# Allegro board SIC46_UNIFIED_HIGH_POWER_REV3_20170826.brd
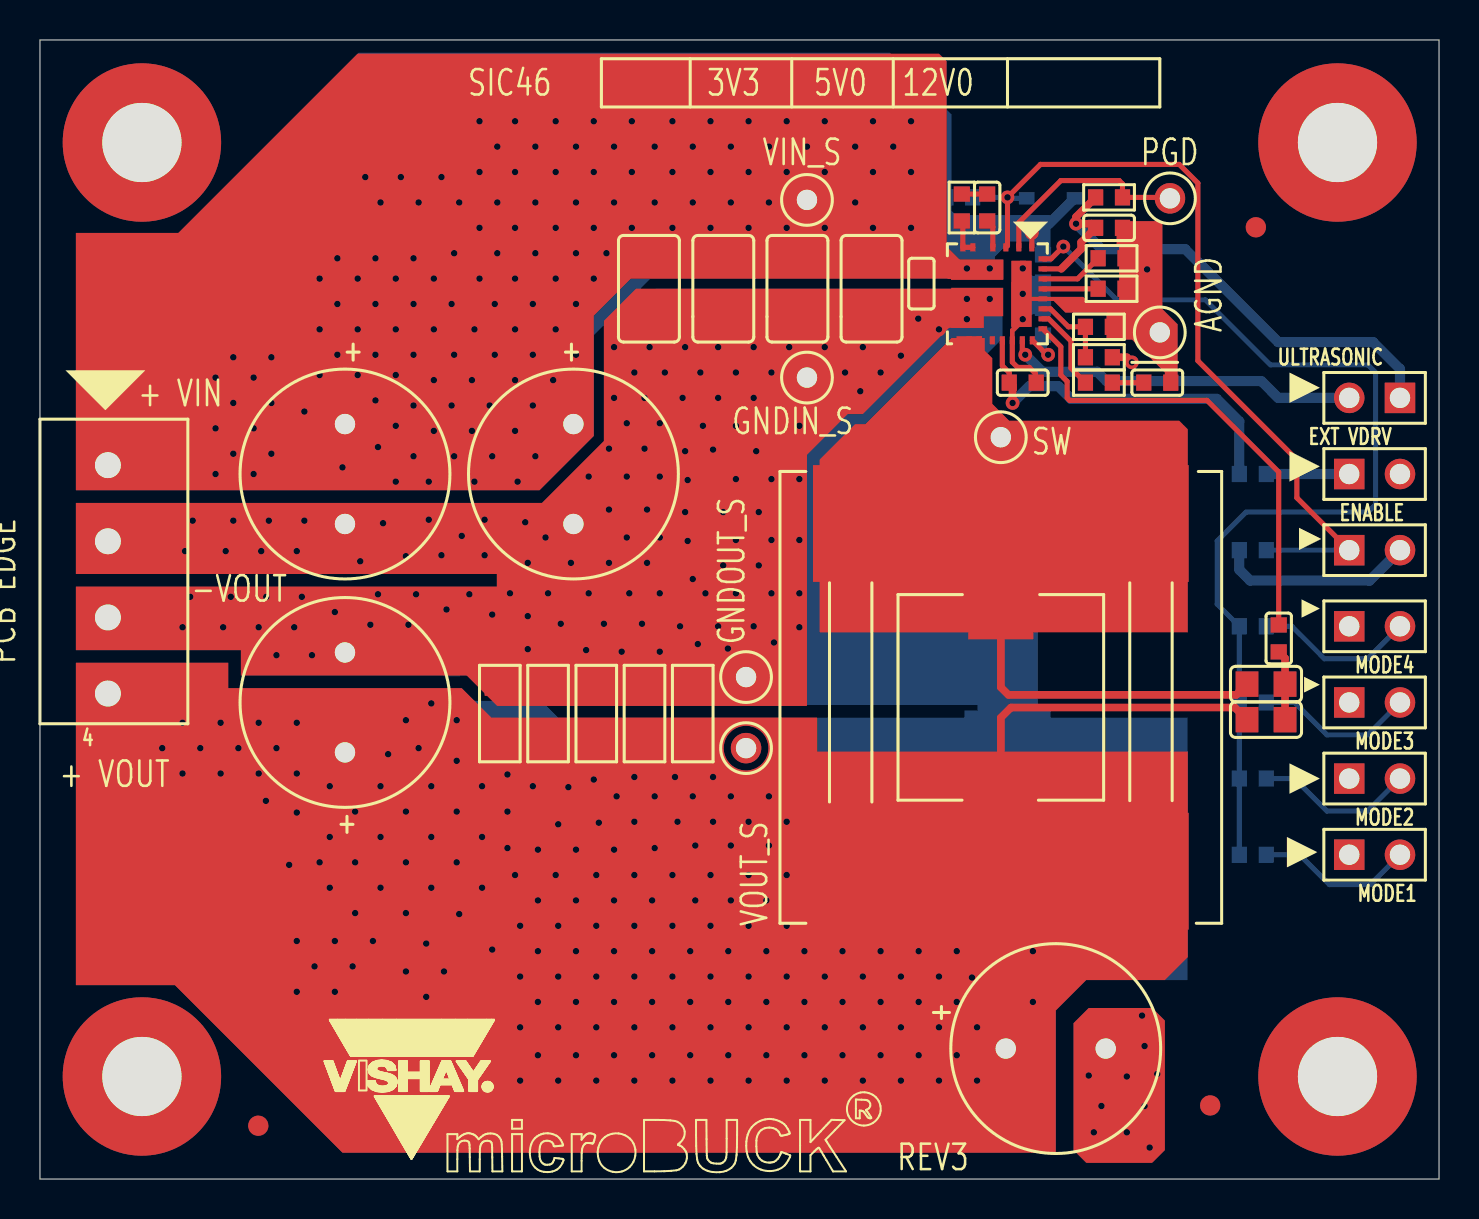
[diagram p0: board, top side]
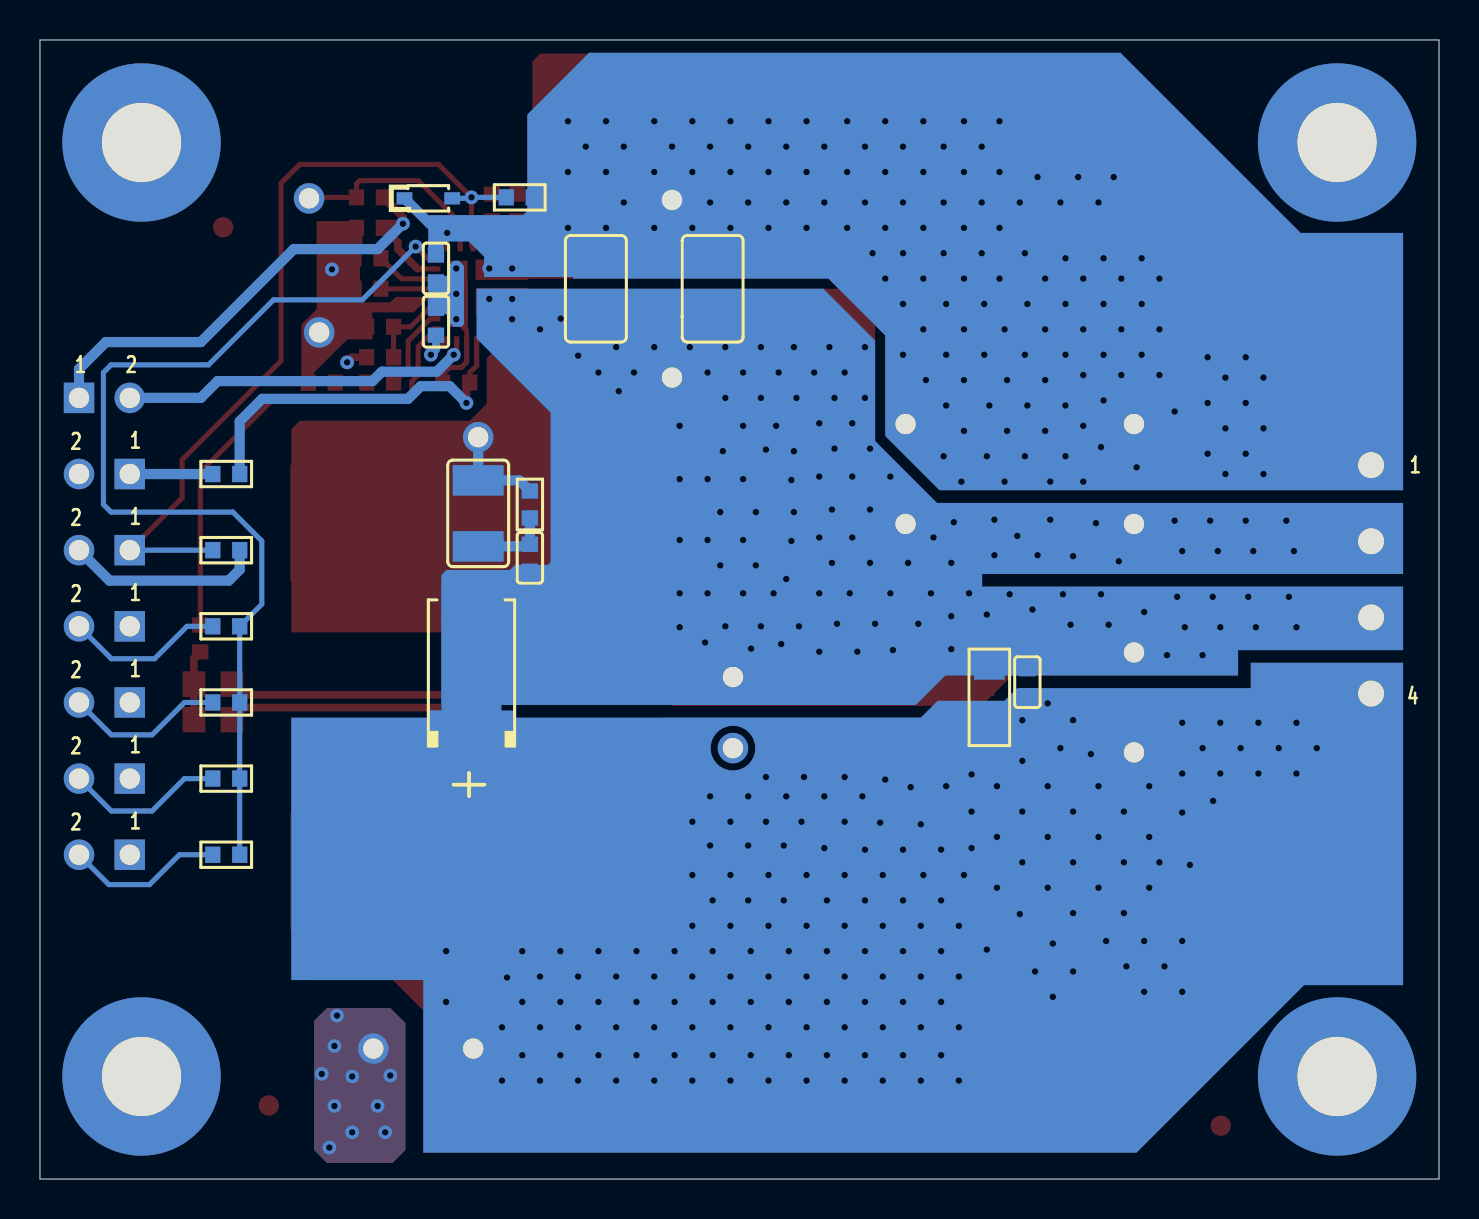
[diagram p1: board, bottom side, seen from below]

Outline 70 x 57 mm; copper layers: TOP, INNER_LAYER2, INNER_LAYER3, INNER_LAYER4, INNER_LAYER5, BOTTOM. Coordinates in mm from the lower left corner of the outline.
Outline path: 0,57 0,0 70,0 70,57 0,57

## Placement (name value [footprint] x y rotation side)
C1  0.1uF  [C0603]  47.39 48.61 270 top
C2  0.1uF  [C0603]  50.19 45.56 90 bottom
C3  1uF  [C0603]  53.49 47.6 180 top
C4  2.2uF  [C1210]  36.34 44.55 90 bottom
C5  2.2uF  [C1210]  37.9 44.55 90 top
C6  2.2uF  [C1210]  41.61 44.55 90 top
C7  2.2uF  [C1210]  42.18 44.55 90 bottom
C8  0.1uF  [C0603]  44.1 44.81 270 top
C9  1nF  [C0603]  55.9 39.85 180 top
C10  22nF  [C0603]  50.19 42.9 90 bottom
C11  4.7uF  [C0603]  49.17 39.85 180 top
C12  2.2nF  [C0603]  61.98 27.05 270 top
C13  22nF  [C0805]  61.34 22.99 180 top
C14  0.1uF  [C0603]  20.59 24.86 270 bottom
C15  22uF  [C1206]  30.25 23.29 270 top
C16  22uF  [C1206]  25.42 23.29 270 top
C17  22uF  [C1206]  22.5 24.1 270 bottom
C18  22uF  [C1206]  32.66 23.29 270 top
C19  22uF  [C1206]  23.01 23.29 270 top
C20  22uF  [C1206]  27.83 23.29 270 top
C21  DNP  [C0603]  45.49 31.09 270 bottom
C22  100uF 63V  [MAL215058101E3]  26.69 35.28 270 top
C23  470u, 2V  [T_D27_7343]  48.41 25.32 90 bottom
C24  100uF 63V  [MAL215058101E3]  50.82 6.53 0 top
C25  2.2uF  [C1210]  34.19 44.55 90 top
C26  2.2uF  [C1210]  30.47 44.55 90 top
C27  100uF 63V  [MAL215058101E3]  15.26 23.85 90 top
C28  100uF 63V  [MAL215058101E3]  15.26 35.28 270 top
D1  DNP  [BZX384C3V3]  50.57 49.07 0 bottom
J1  JUMPER  [22-28-4023]  65.5 16.23 0 top
J2  JUMPER  [22-28-4023]  65.5 20.04 0 top
J3  JUMPER  [22-28-4023]  65.5 23.85 0 top
J4  JUMPER  [22-28-4023]  65.5 27.66 0 top
J5  CON4  [20020327-D041B01LF]  3.4 35.72 270 top
J6  PGD  [5002]  56.54 49.07 0 top
J7  EN  [22-28-4023]  65.5 35.28 0 top
J8  JUMPER  [22-28-4023]  68.04 39.09 180 top
J9  EN  [22-28-4023]  65.5 31.47 0 top
J10  GND  [5002]  56.03 42.36 0 top
L1  DNP  [IHLP-4040]  48.07 24.1 90 top
L2  3.3uH  [IHLP-5050]  48.07 24.1 90 top
L3  DNP  [IHLP-6767]  48.07 24.1 90 top
L4  DNP  [IHLP-8787]  48.07 24.1 180 top
NOREF  -  []  16.47 44.29 0 top
NOREF#2  -  []  70.74 -17.94 90 top
NOREF#3  -  []  33.17 -43.2 90 top
NOREF#4  -  []  70 0 90 top
NOREF#5  -  []  126.76 1.25 0 top
NOREF#6  -  [unnamed#2]  58.55 3.68 0 top
NOREF#7  -  []  33.17 6.33 90 top
NOREF#8  -  []  38.82 1.68 90 top
NOREF#9  -  []  146.18 -25.56 90 top
NOREF#10  -  []  81.94 73 0 top
NOREF#11  -  []  210.87 -24.79 0 top
NOREF#12  -  []  159.41 73 90 top
NOREF#13  -  []  119.04 -0.16 90 top
NOREF#14  -  []  173.38 73 0 top
NOREF#15  -  []  10.82 -47.85 0 top
NOREF#16  -  []  33.17 31.09 90 top
NOREF#17  -  []  70.74 -43.34 90 top
NOREF#18  -  []  33.17 55.86 90 top
NOREF#19  -  []  158.41 74.5 90 top
NOREF#20  -  [unnamed#2]  60.83 47.62 0 top
NOREF#21  -  []  146.18 7.46 0 top
NOREF#22  -  []  144.44 76 0 top
NOREF#23  -  []  0 38.02 0 top
NOREF#24  -  []  22.82 19.53 0 top
NOREF#25  -  []  130.11 -10.9 0 top
NOREF#26  -  []  119.04 -17.94 90 top
NOREF#27  -  []  29.17 -5.24 0 top
NOREF#28  -  []  3.4 35.72 90 top
NOREF#29  -  []  146.18 -35.72 90 top
NOREF#30  -  []  10.82 -23.09 0 top
NOREF#31  -  []  74.57 29.05 0 top
NOREF#32  -  []  29.17 19.53 0 top
NOREF#33  -  []  22.82 44.29 0 top
NOREF#34  -  []  16.47 69.06 0 top
NOREF#35  -  []  10.82 1.68 0 top
NOREF#36  -  []  16.47 19.53 0 top
NOREF#37  -  []  29.17 -30 0 top
NOREF#38  -  []  10.82 51.21 0 top
NOREF#39  -  []  0 57 0 top
NOREF#40  -  []  159.41 73 0 top
NOREF#41  -  []  70.74 -43.34 0 top
NOREF#42  -  []  80.94 74.5 90 top
NOREF#43  -  []  119.04 -17.94 90 top
NOREF#44  -  []  194.48 -43.34 90 top
NOREF#45  -  []  146.18 -25.56 90 top
NOREF#46  -  [unnamed#2]  64.92 5.13 0 top
NOREF#47  -  [unnamed#2]  5.1 51.87 0 top
NOREF#48  -  []  145.44 73 90 top
NOREF#49  -  []  205.1 -35.23 0 top
NOREF#50  -  []  173.38 73 90 top
NOREF#51  -  [unnamed#2]  64.92 51.87 0 top
NOREF#52  -  []  119.04 -35.72 90 top
NOREF#53  -  []  146.18 -10.32 90 top
NOREF#54  -  []  29.17 69.06 0 top
NOREF#55  -  []  15.24 38.02 90 top
NOREF#56  -  []  194.48 -17.94 90 top
NOREF#57  -  []  3.4 31.91 90 top
NOREF#58  -  []  145.44 73 0 top
NOREF#59  -  []  38.82 -23.09 90 top
NOREF#60  -  []  38.82 -47.85 90 top
NOREF#61  -  []  144.44 74.5 90 top
NOREF#62  -  []  119.04 -10.32 90 top
NOREF#63  -  []  80.94 76 0 top
NOREF#64  -  []  67.97 73 90 top
NOREF#65  -  [unnamed#2]  5.1 5.13 0 top
NOREF#66  -  []  66.97 76 0 top
NOREF#67  -  []  33.17 -18.44 90 top
NOREF#68  -  []  130.45 2.13 90 top
NOREF#69  -  []  70.74 -28.1 90 top
NOREF#70  -  []  22.82 -5.24 0 top
NOREF#71  -  []  146.18 -17.94 90 top
NOREF#72  -  []  131.29 -7.52 0 top
NOREF#73  -  []  -25.63 -29.6 0 top
NOREF#74  -  []  0 45.42 0 top
NOREF#75  -  []  146.18 -43.34 90 top
NOREF#76  -  []  22.82 -30 0 top
NOREF#77  -  []  194.48 -28.1 90 top
NOREF#78  -  []  172.38 76 0 top
NOREF#79  -  []  68.79 18.62 0 top
NOREF#80  -  []  81.94 73 90 top
NOREF#81  -  []  29.17 44.29 0 top
NOREF#82  -  []  132.74 -40.21 90 top
NOREF#83  -  []  172.38 74.5 90 top
NOREF#84  -  []  38.82 51.21 90 top
NOREF#85  -  []  66.97 74.5 90 top
NOREF#86  -  []  10.82 26.44 0 top
NOREF#87  -  []  -57.13 -63.4 0 top
NOREF#88  -  []  158.41 76 0 top
NOREF#89  -  []  38.82 26.44 90 top
NOREF#90  -  [unnamed#2]  10.92 2.67 0 top
NOREF#91  -  []  22.82 69.06 0 top
NOREF#92  -  []  67.97 73 0 top
NOREF#93  -  []  119.04 -25.56 90 top
NOREF#94  -  []  16.47 -5.24 0 top
NOREF#95  -  []  129.05 -41.09 0 top
NOREF#96  -  []  16.47 -30 0 top
R1  102K  [R0603]  53.49 49.12 180 top
R2  3.3  [R0603]  46.12 48.61 90 top
R3  560K  [R0603]  45.99 49.12 0 bottom
R4  53.6K  [R0603]  53.61 46.07 180 top
R5  2K  [R0603]  60.68 16.23 0 bottom
R6  301K  [R0603]  60.68 20.04 0 bottom
R7  499K  [R0603]  60.68 23.85 0 bottom
R8  1M  [R0603]  60.68 27.66 0 bottom
R9  53.6K  [R0603]  53.61 44.55 180 top
R10  10K  [R0603]  52.98 42.64 180 top
R11  19.6K  [R0603]  52.98 39.85 180 top
R12  52.3K  [R0603]  52.98 41.12 0 top
R14  DNP  [R0603]  60.68 35.28 180 bottom
R15  DNP  [R0805]  61.34 24.77 180 top
R16  DNP  [R0603]  45.49 33.75 270 bottom
R16A  DNP  [R1210]  48.07 33.31 270 bottom
R17  DNP  [R0603]  60.68 31.47 0 bottom
TP1  test point  [5002]  38.37 48.99 0 top
TP2  test point  [5002]  38.37 40.1 0 top
TP3  test point  [5002]  35.33 21.56 0 top
TP4  test point  [5002]  35.33 25.12 90 top
TP11  5002  [PAD040_060_SQ]  48.07 37.12 0 top
U1  SiC46X  [5MMX5MM]  47.9 44.29 270 top

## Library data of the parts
C1-C21 C25 C26 = CAP NP
C22 C24 C27 C28 = CAP POL
C23 = CAP, TA-P,V,470u, 2V_0: User Part Number: PN; Tolerance: TOL
D1 = DIODE ZENER
J1-J4 J8 = JUMPER
J5 = HEADER 4
J6 J10 = HEADER 1
J7 J9 = HEADER 2
L1-L4 = IND
R1-R12 R14-R16 R16A R17 = RESISTOR
TP1-TP4 = TEST POINT
TP11 = TP_0
U1 = SiC462CD-T1-GE3_32

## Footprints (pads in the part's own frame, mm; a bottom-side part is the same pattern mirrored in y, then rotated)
5MMX5MM
  rect 0.406x0.254 smd: 1(-2.325,1.725) 2(-2.325,1.075) 3(-2.325,0.425) 4(-2.325,-0.225) 5(-2.325,-1.225) 6(-2.325,-1.725) 13(2.325,-1.4) 14(2.325,-0.9) 15(2.325,-0.25) 16(2.325,0.25) 17(2.325,0.75) 18(2.325,1.25) 19(2.325,1.75)
  rect 0.254x0.432 smd: 7(-1.525,-2.275) 8(-0.875,-2.275) 9(0.25,-2.275) 10(0.75,-2.275) 11(1.25,-2.275) 20(1.75,2.275) 21(1.25,2.275) 22(0.75,2.275) 23(0.25,2.275) 24(-0.25,2.275) 25(-0.75,2.275) 26(-1.25,2.275) 27(-1.75,2.275)
  rect 0.406x1.27 smd: 12(2.325,-1.408)
  rect 3.302x1.016 smd: 28(0,1.208)
  rect 1.016x2.616 smd: 29(-1.208,-1.008)
  custom 0.5x0.5 smd: 30(0.7,-1.008)
22-28-4023
  rect 1.524x1.524 hole 1.016: 1(0,0)
  round 1.524 hole 1.016: 2(2.54,0)
5002
  round 1.524 hole 1.016: 1(0,0)
20020327-D041B01LF
  rect 2.057x2.057 hole 1.295: 1(0,0)
  round 2.057 hole 1.295: 2(3.81,0) 3(7.62,0) 4(11.43,0)
BZX384C3V3
  rect 0.787x0.61 smd: 1(1.194,0) 2(-1.194,0)
C0603
  rect 0.762x0.813 smd: 1(-0.673,0) 2(0.673,0)
C0805
  rect 1.143x1.27 smd: 1(-0.953,0) 2(0.953,0)
C1206
  rect 1.27x1.524 smd: 1(-1.524,0) 2(1.524,0)
C1210
  rect 1.524x2.54 smd: 1(-1.651,0) 2(1.651,0)
IHLP-4040
  rect 3.124x3.251 smd: 1(-4.47,0) 2(4.47,0)
IHLP-5050
  rect 3.175x3.251 smd: 1(-5.715,0) 2(5.715,0)
IHLP-6767
  rect 3.81x12.319 smd: 1(-8.077,0) 2(8.077,0)
IHLP-8787
  rect 18.796x5.842 smd: 1(0,8.7) 2(0,-8.7)
MAL215058101E3
  rect 1.524x1.524 hole 1.016: 1(-2.5,0)
  round 1.524 hole 1.016: 2(2.5,0)
PAD040_060_SQ
  round 1.524 hole 1.016: 1(0,0)
R0603
  rect 0.762x0.813 smd: 1(-0.673,0) 2(0.673,0)
R0805
  rect 1.143x1.27 smd: 1(-0.953,0) 2(0.953,0)
R1210
  rect 1.524x2.54 smd: 1(-1.651,0) 2(1.651,0)
T_D27_7343
  rect 2.134x2.997 smd: 1(-3.429,0) 3(3.429,0)
  custom 1.079x1.079 smd: 2(0,0)
unnamed#2
  round 1.016 smd: 1(0,0)

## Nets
GND: C4.1 C5.1 C6.1 C7.1 C8.2 C14.1 C15.1 C16.1 C17.1 C18.1 C19.1 C20.1 C21.2 C22.2 C23.2 C23.3 C24.2 C25.1 C26.1 C27.2 C28.2 J5.2 J5.3 J7.2 TP2.1 TP4.1 U1.9(PGND1) U1.10(PGND2) U1.11(PGND3) U1.30(PGND-PAD)
GND_SIGNAL: C2.1 C3.1 C9.1 C10.2 C11.1 J1.1 J2.1 J3.1 J4.1 J9.2 J10.1 R4.1 R9.1 R10.1 R17.1 U1.17(CDRV_RTN) U1.23(AGND) U1.28(AGND-PAD)
VDD1: C3.2 J8.1 R1.2 U1.26(VDD)
VIN: C2.2 C4.2 C5.2 C6.2 C7.2 C8.1 C22.1 C25.2 C26.2 C28.1 D1.1(CATHODE) J5.1 R3.1 TP1.1 U1.1(VCIN) U1.7(VIN1) U1.8(VIN2) U1.29(VIN-PAD)
BOOT: C1.2 U1.4(BOOT)
COMP: R11.2 U1.21(COMP)
ENABLE: D1.2(ANODE) J9.1 R3.2 R17.2 U1.3(EN)
FSW: R9.2 U1.24(FSW)
ILIM: R4.2 U1.25(ILIMIT)
MODE: R5.1 R6.1 R7.1 R8.1 U1.27(MODE)
PGD: J6.1 R1.1 U1.2(PGOOD)
SS: C10.1 U1.19(SS)
ULTRASONIC: J8.2 U1.18(ULTRASONIC)
VDRV: C11.2 R14.2 U1.16(VDRV)
VDRV_IN: J7.1 R14.1
VFB: R10.2 R12.1 U1.22(VFB)
VO: C13.2 C14.2 C15.2 C16.2 C17.2 C18.2 C19.2 C20.2 C23.1 C24.1 C27.1 J5.4 L1.1(A) L2.1(A) L3.1(A) L4.1(A) R12.2 TP3.1
N16770186: R2.1 U1.5(PHASE1) U1.6(PHASE2)
N16770229: C1.1 R2.2
N16771868: C9.2 R11.1
N16772198: J1.2 R5.2
N16772202: J2.2 R6.2
N16772206: J3.2 R7.2
N16773012: C12.2 C13.1 R15.1
N16775181: L1.2(B) L2.2(B) L3.2(B) L4.2(B) R15.2 R16.1 R16A.1 TP11.1 U1.12(SW1) U1.13(SW2) U1.14(SW3)
N16812890: C21.1 R16.2 R16A.2
N16829136: J4.2 R8.2
N16842327: C12.1 U1.20(VSNS)

Pads without a net: NOREF#6 1; NOREF#20 1; NOREF#46 1; NOREF#47 1; NOREF#51 1; NOREF#65 1; NOREF#90 1; U1 15

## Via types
v1: diameter 0.686, hole 0.33, TOP to BOTTOM, 467 vias

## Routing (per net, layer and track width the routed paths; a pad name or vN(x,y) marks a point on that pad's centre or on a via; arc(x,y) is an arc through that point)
GND:
  vias: v1(7.13,27.61) v1(7.26,31.42) v1(7.51,29.13) v1(7.64,32.94) v1(9.16,27.61) v1(9.29,31.42) v1(9.55,29.13) v1(9.67,32.94) v1(10.94,27.61) v1(11.07,31.42) v1(11.32,29.13) v1(11.45,32.94) v1(11.83,26.21) v1(12.72,27.61) v1(12.85,31.42) v1(13.1,29.13) v1(13.23,32.94) v1(13.61,26.21) v1(14.75,28.37) v1(16.02,30.91) v1(16.53,27.74) v1(16.91,29.26) v1(17.17,32.82) v1(18.31,31.17) v1(18.44,27.74) v1(18.82,29.26) v1(19.45,32.99) v1(20.09,31.21) v1(20.34,28.5) v1(21.1,32.18) v1(21.48,29.26) v1(22.25,32.99) v1(22.25,31.21) v1(22.63,28.24) v1(23.52,29.31) v1(24.28,32.86) v1(24.4,30.83) v1(24.4,28.17) v1(24.4,26.51) v1(25.29,32.1) v1(25.42,29.31) v1(26.06,27.78) v1(26.56,30.83) v1(27.33,26.47) v1(27.45,35.15) v1(27.45,29.31) v1(28.21,27.78) v1(28.47,36.55) v1(28.47,33.5) v1(28.47,30.83) v1(28.72,41.63) v1(28.72,39.09) v1(29.1,26.39) v1(29.36,37.82) v1(29.36,35.15) v1(29.36,32.1) v1(29.48,29.31) v1(29.74,40.36) v1(30.12,27.78) v1(30.25,39.09) v1(30.25,36.55) v1(30.37,33.5) v1(30.37,30.83) v1(30.5,41.63) v1(31.01,37.82) v1(31.01,35.15) v1(31.01,32.1) v1(31.01,29.31) v1(31.01,26.39) v1(31.26,40.36) v1(32.02,27.66) v1(32.15,39.09) v1(32.28,41.63) v1(32.28,36.42) v1(32.28,33.37) v1(32.41,34.98) v1(32.41,31.93) v1(32.66,30.02) v1(32.91,26.77) v1(33.04,40.36) v1(33.17,37.69) v1(33.29,29.31) v1(33.68,36.5) v1(33.93,41.63) v1(33.93,39.09) v1(33.93,27.66) v1(34.18,33.37) v1(34.18,30.71) v1(34.42,26.54) v1(34.82,40.36) v1(34.82,37.69) v1(34.82,35.02) v1(34.82,31.98) v1(34.82,29.31) v1(35.71,41.63) v1(35.71,39.09) v1(35.71,27.66) v1(35.83,36.42) v1(35.96,33.37) v1(35.96,30.71) v1(36.6,40.36) v1(36.6,35.02) v1(36.6,31.98) v1(36.6,29.31) v1(36.72,26.85) v1(37.49,41.63) v1(37.99,37.69) v1(37.99,35.02) v1(37.99,31.98) v1(37.99,29.31) v1(37.99,27.61) v1(39.26,41.63) v1(40.28,40.36) v1(41.04,39.42) v1(41.17,41.63) v1(42.06,40.36) v1(43.07,41.2) v1(43.94,43.05) v1(44.98,42.52) v1(46.38,44.04) v1(46.38,43.02) v1(47.52,44.04) v1(52.47,5.18) v1(52.73,2.34) v1(53.11,3.65) v1(54.38,5.13) v1(54.38,2.34) v1(55.14,8.18) v1(55.27,6.65) v1(55.27,3.65) v1(55.52,1.57) v1(55.9,5.26)
GND_SIGNAL: length 12.8
  TOP w0.254: C11.1 49.8,39.89 49.8,40.31 49.5,40.61 48.92,40.61 48.65,40.88 U1.17
  BOTTOM w0.508: R17.1 60.01,30.49 60.55,29.94 66.52,29.94 J9.2
  vias: v1(49.17,45.56) v1(49.17,44.29) v1(49.17,43.02) v1(55.39,45.52)
VDD1: length 27.1
  TOP w0.254: 51.1,45.54 U1.26
  TOP w0.381: 51.1,45.54 52.09,46.53 52.09,46.87 C3.2 52.61,47.8 v1(51.84,47.8) 51.84,48.14 R1.2
  BOTTOM w0.508: v1(51.84,47.8) 53.11,46.53 57.3,46.53 61.95,41.88 66.7,41.88 68.04,40.53 J8.1
VIN: length 2.7
  TOP w0.254: U1.1 v1(49.62,47.34)
  BOTTOM w0.508: D1.1 50.49,47.8 50.31,47.8
  vias: v1(8.78,40.1) v1(8.78,37.56) v1(8.78,35.28) v1(9.67,41.12) v1(9.67,38.83) v1(9.67,36.29) v1(10.69,40.1) v1(10.69,37.56) v1(10.69,35.28) v1(11.58,41.12) v1(11.58,38.83) v1(11.58,36.29) v1(13.23,38.4) v1(13.99,45.06) v1(13.99,42.52) v1(13.99,40.23) v1(14.88,46.07) v1(14.88,43.79) v1(14.88,41.25) v1(15.13,35.61) v1(15.9,45.06) v1(15.9,42.52) v1(15.9,40.23) v1(16.28,50.14) v1(16.78,46.07) v1(16.78,43.79) v1(16.78,41.25) v1(16.78,38.96) v1(16.91,36.63) v1(17.04,48.87) v1(17.8,45.06) v1(17.8,42.52) v1(17.8,40.23) v1(17.8,37.69) v1(17.8,34.9) v1(18.05,50.14) v1(18.69,46.07) v1(18.69,43.79) v1(18.69,41.25) v1(18.69,38.71) v1(18.69,36.17) v1(18.94,48.87) v1(19.45,34.9) v1(19.71,45.06) v1(19.71,42.52) v1(19.71,39.98) v1(19.71,37.44) v1(20.09,50.14) v1(20.59,43.79) v1(20.59,38.71) v1(20.72,46.33) v1(20.72,41.25) v1(20.72,36.17) v1(20.98,48.87) v1(21.61,39.98) v1(21.61,37.44) v1(21.74,42.52) v1(21.74,34.9) v1(21.99,52.93) v1(21.99,50.39) v1(21.99,47.6) v1(21.99,45.06) v1(22.5,38.71) v1(22.63,36.17) v1(22.75,43.79) v1(22.75,41.25) v1(22.88,51.66) v1(22.88,48.87) v1(22.88,46.33) v1(23.77,52.93) v1(23.77,50.39) v1(23.77,47.6) v1(23.77,45.06) v1(23.77,42.52) v1(23.77,39.98) v1(23.77,37.44) v1(23.9,34.9) v1(24.66,43.79) v1(24.66,41.25) v1(24.66,38.71) v1(24.79,51.66) v1(24.79,48.87) v1(24.79,46.33) v1(24.79,36.17) v1(25.67,39.98) v1(25.8,52.93) v1(25.8,50.39) v1(25.8,47.6) v1(25.8,45.06) v1(25.8,42.52) v1(26.82,51.66) v1(26.82,48.87) v1(26.82,46.33) v1(26.82,43.79) v1(26.82,41.25) v1(27.71,52.93) v1(27.71,50.39) v1(27.71,47.6) v1(27.71,45.06) v1(28.34,46.33) v1(28.72,51.66) v1(28.72,48.87) v1(29.61,52.93) v1(29.61,50.39) v1(29.61,47.6) v1(30.75,51.66) v1(30.75,48.87) v1(31.64,52.93) v1(31.64,50.39) v1(31.64,47.6) v1(32.66,51.66) v1(32.66,48.87) v1(33.55,52.93) v1(33.55,50.39) v1(33.55,47.6) v1(34.56,51.66) v1(34.56,48.87) v1(35.45,52.93) v1(35.45,50.39) v1(35.45,47.6) v1(36.47,51.66) v1(36.47,48.87) v1(37.36,52.93) v1(37.36,50.39) v1(37.36,47.6) v1(38.37,51.66) v1(39.26,52.93) v1(39.26,50.39) v1(39.26,47.6) v1(40.79,51.66) v1(40.79,48.87) v1(41.68,52.93) v1(41.68,50.39) v1(41.68,47.6) v1(42.69,51.66) v1(43.58,52.93) v1(43.58,50.39) v1(43.58,47.6) v1(46.38,45.56) v1(47.52,45.56)
BOOT: length 1.4
  TOP w0.254: C1.2 47.67,47.66 U1.4
COMP: length 4.3
  TOP w0.254: R11.2 51.58,40.57 51.58,41.93 50.47,43.04 U1.21
ENABLE: length 41.5
  TOP w0.254: J9.1 62.89,34.09 62.89,35.99 57.93,40.94 57.93,49.83 57,50.77 50.06,50.77 v1(48.41,49.12) 48.41,46.7 U1.3
  BOTTOM w0.254: D1.2 48.46,49.07 v1(48.41,49.12) R3.2 ; R17.2 J9.1
FSW: length 2.8
  TOP w0.254: U1.24 52.94,44.54 R9.2
ILIM: length 3.2
  TOP w0.254: R4.2 51.91,45.04 U1.25
MODE: length 51
  TOP w0.254: U1.27 50.59,46.04 v1(51.2,46.66)
  BOTTOM w0.254: v1(51.2,46.66) 53.87,43.99 58.31,43.99 61.57,40.74 66.44,40.74 66.82,40.36 66.82,33.75 66.44,33.37 60.35,33.37 58.9,31.93 58.9,28.76 R8.1 R7.1 R6.1 R5.1
PGD: length 10.4
  TOP w0.254: J6.1 56.49,49.12 R1.1 54.16,49.8 54,49.96 51.07,49.96 48.97,47.86 U1.2
SS: length 2.2
  TOP w0.254: v1(50.44,41.25) 50.37,41.25 U1.19
  BOTTOM w0.381: C10.1 50.19,41.5 v1(50.44,41.25)
ULTRASONIC: length 17.9
  TOP w0.254: U1.18 49.15,41.39 v1(49.3,41.25)
  BOTTOM w0.508: J8.2 61.95,39.09 61.11,39.93 53.36,39.93 52.89,40.4 50.15,40.4 v1(49.3,41.25)
VDRV: length 18.4
  TOP w0.254: U1.16 48.15,40.69 48.5,40.35 C11.2
  TOP w0.381: v1(48.66,38.83) 48.66,39.68 C11.2
  BOTTOM w0.508: v1(48.66,38.83) 49.5,39.67 50.95,39.67 51.58,39.04 58.88,39.04 60.01,37.91 R14.2
VDRV_IN: length 4.2
  BOTTOM w0.508: J7.1 R14.1
VFB: length 4
  TOP w0.254: U1.22 50.55,43.54 51.46,42.64 R10.2 R12.1
VO: length 101.7
  TOP w0.381: C13.2 59.78,23.59 48.58,23.59 48.07,23.08 L1.1 L2.1 L3.1 ; R12.2 54.38,41.12 v1(54.63,40.87)
  INNER_LAYER3 w0.508: v1(54.63,40.87) 59.69,35.81 59.69,21.21 58.85,20.37 36.52,20.37 TP3.1 35.33,22.71 34.87,23.16 26.06,23.16 24.2,25.02 4.68,25.02 3.96,24.29
  vias: v1(6.12,21.56) v1(7.13,22.83) v1(7.13,20.29) v1(8.02,21.56) v1(9.04,22.83) v1(9.04,20.29) v1(9.93,21.56) v1(10.94,22.83) v1(10.94,20.29) v1(11.3,18.92) v1(11.83,21.56) v1(12.47,15.72) v1(12.85,22.83) v1(12.85,20.29) v1(12.85,18.34) v1(12.85,11.91) v1(12.85,9.37) v1(13.74,10.64) v1(13.99,15.85) v1(14.5,19.66) v1(14.5,17.12) v1(14.5,14.58) v1(14.75,11.91) v1(14.75,9.37) v1(15.64,10.64) v1(15.77,18.39) v1(15.77,15.85) v1(15.77,13.31) v1(16.66,11.91) v1(17.04,19.66) v1(17.04,17.12) v1(17.04,14.58) v1(17.42,21.26) v1(18.31,22.96) v1(18.31,18.39) v1(18.31,15.85) v1(18.31,13.31) v1(18.31,10.39) v1(18.94,21.56) v1(19.32,11.78) v1(19.32,9.12) v1(19.58,23.8) v1(19.58,19.66) v1(19.58,17.12) v1(19.58,14.58) v1(20.21,10.39) v1(20.85,22.96) v1(20.85,20.93) v1(20.85,18.39) v1(20.85,15.85) v1(20.98,13.26) v1(22.12,19.66) v1(22.12,17.12) v1(22.12,14.58) v1(22.63,11.48) v1(23.39,20.24) v1(23.39,18.39) v1(23.39,16.56) v1(23.77,15.21) v1(24.02,12.67) v1(24.02,10.13) v1(24.02,7.59) v1(24.02,4.92) v1(24.66,19.66) v1(24.91,16.48) v1(24.91,13.94) v1(24.91,11.4) v1(24.91,8.86) v1(24.91,6.19) v1(25.8,15.21) v1(25.93,17.75) v1(25.93,12.67) v1(25.93,10.13) v1(25.93,7.59) v1(25.93,4.92) v1(26.44,19.61) v1(26.82,16.48) v1(26.82,13.94) v1(26.82,11.4) v1(26.82,8.86) v1(26.82,6.19) v1(27.71,19.99) v1(27.83,15.21) v1(27.83,12.67) v1(27.83,10.13) v1(27.83,7.59) v1(27.83,4.92) v1(27.96,17.83) v1(28.72,16.48) v1(28.72,13.94) v1(28.72,11.4) v1(28.72,8.86) v1(28.72,6.19) v1(28.85,19.15) v1(29.74,20.12) v1(29.74,17.88) v1(29.74,15.21) v1(29.74,12.67) v1(29.74,10.13) v1(29.74,7.59) v1(29.74,4.92) v1(30.63,13.94) v1(30.63,11.4) v1(30.63,8.86) v1(30.63,6.19) v1(30.75,19.15) v1(30.75,16.56) v1(31.64,15.21) v1(31.64,12.67) v1(31.64,10.13) v1(31.64,7.59) v1(31.64,4.92) v1(31.77,20.12) v1(31.9,17.88) v1(32.53,11.4) v1(32.53,8.86) v1(32.53,6.19) v1(32.66,19.15) v1(32.79,16.69) v1(32.79,13.94) v1(33.55,15.21) v1(33.55,12.67) v1(33.55,10.13) v1(33.55,7.59) v1(33.55,4.92) v1(33.68,20.12) v1(33.68,17.88) v1(34.44,11.4) v1(34.44,8.86) v1(34.44,6.19) v1(34.56,19.15) v1(34.56,16.69) v1(34.56,13.94) v1(35.45,17.88) v1(35.45,15.21) v1(35.45,12.67) v1(35.45,10.13) v1(35.45,7.59) v1(35.45,4.92) v1(36.34,13.94) v1(36.34,11.4) v1(36.34,8.86) v1(36.34,6.19) v1(36.47,19.15) v1(36.47,16.69) v1(37.36,17.88) v1(37.36,15.21) v1(37.36,12.67) v1(37.36,10.13) v1(37.36,7.59) v1(37.36,4.92) v1(38.25,11.4) v1(38.25,8.86) v1(38.25,6.19) v1(39.26,10.13) v1(39.26,7.59) v1(39.26,4.92) v1(40.15,11.4) v1(40.15,8.86) v1(40.15,6.19) v1(41.17,10.13) v1(41.17,7.59) v1(41.17,4.92) v1(42.06,11.4) v1(42.06,8.86) v1(42.06,6.19) v1(43.07,10.13) v1(43.07,7.59) v1(43.07,4.92) v1(43.96,11.4) v1(43.96,8.86) v1(43.96,6.19) v1(44.98,10.13) v1(44.98,7.59) v1(44.98,4.92) v1(45.87,11.4) v1(45.87,8.86) v1(45.87,6.19) v1(46.63,10.08) v1(46.88,7.59) v1(46.88,4.92) v1(49.68,11.4) v1(49.68,8.86)
N16770186: length 1.8
  TOP w0.254: U1.5 U1.6 46.17,47.89 R2.1
N16770229: length 1.3
  TOP w0.254: C1.1 R2.2
N16771868: length 1.6
  TOP w0.254: C9.2 R11.1
N16772198: length 7.9
  BOTTOM w0.254: R5.2 63.02,16.23 64.52,14.73 66.55,14.73 J1.2
N16772202: length 8
  BOTTOM w0.254: R6.2 62.77,20.04 64.39,18.41 66.42,18.41 J2.2
N16772206: length 8
  BOTTOM w0.254: R7.2 62.77,23.85 64.39,22.23 66.42,22.23 J3.2
N16773012: length 3.5
  TOP w0.381: C12.2 62.29,26.06 R15.1 C13.1
N16775181: length 25.9
  TOP w0.381: R15.2 59.85,24.23 48.45,24.23 48.07,24.61 L1.2 L2.2 L3.2 L4.2
  BOTTOM w0.508: TP11.1 R16A.1 46.02,34.96 R16.1
N16812890: length 3.9
  BOTTOM w0.508: R16.2 C21.1 45.59,31.66 R16A.2
N16829136: length 8
  BOTTOM w0.254: R8.2 62.64,27.66 64.26,26.04 66.42,26.04 J4.2
N16842327: length 23.7
  TOP w0.254: U1.20 51.07,41.64 51.07,40.23 51.39,39.91 51.39,39.09 51.52,38.96 58.39,38.96 61.98,35.38 C12.1

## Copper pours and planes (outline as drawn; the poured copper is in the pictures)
GND on TOP (solid shape): 56.28,7.92 56.28,1.45 55.65,0.81 52.34,0.81 51.71,1.45 51.71,7.8 52.47,8.56 55.65,8.56
GND on TOP (solid shape): 48.15,43.28 47.14,43.28 47.14,42.6 45.49,42.6 41.17,38.28 40.41,38.28 38.37,36.25 38.37,23.67 22.88,23.67 21.36,25.2 10.05,25.2 10.05,26.47 1.8,26.47 1.8,29.64 22.86,29.64 22.86,30.28 1.8,30.28 1.8,33.83 25.12,33.83 28.21,36.93 28.21,42.95 29.82,44.55 48.15,44.55
GND on BOTTOM (solid shape): 48.15,42.06 44.45,38.35 44.45,30.86 44.58,30.73 46.23,30.73 46.48,30.48 49.66,30.48 49.91,30.23 49.91,23.72 26.18,23.72 24.71,25.2 10.05,25.2 10.05,26.47 1.8,26.47 1.8,29.64 22.86,29.64 22.86,30.28 1.8,30.28 1.8,33.83 25.12,33.83 28.21,36.93 28.21,41.96 30.8,44.55 48.15,44.55
GND on BOTTOM: 51.71,7.8 51.71,1.45 52.34,0.81 55.65,0.81 56.28,1.45 56.28,7.92 55.65,8.56 52.47,8.56
GND on INNER_LAYER2: 8.89,0.64 8.89,7.49 0.64,7.49 0.64,29.64 22.86,29.64 22.86,30.28 0.64,30.28 0.64,49.58 9.02,49.58 9.02,56.33 60.71,56.33 60.71,41.53 69.34,41.53 69.34,9.07 61.59,9.07 61.59,0.64
GND on INNER_LAYER3: 8.89,0.64 8.89,8.94 0.64,8.94 0.64,29.64 22.86,29.64 22.86,30.28 0.64,30.28 0.64,46.02 23.39,46.02 23.39,56.33 60.96,56.33 60.96,47.88 69.34,47.88 69.34,9.07 61.09,9.07 61.09,0.64
GND on INNER_LAYER4: 8.89,0.64 8.89,8.94 0.64,8.94 0.64,29.64 22.86,29.64 22.86,30.28 0.64,30.28 0.64,46.02 23.39,46.02 23.39,56.33 60.96,56.33 60.96,47.75 69.34,47.75 69.34,9.07 61.09,9.07 61.09,0.64
GND on INNER_LAYER5: 8.89,0.64 8.89,8.94 0.64,8.94 0.64,29.64 22.86,29.64 22.86,30.28 0.64,30.28 0.64,46.02 23.39,46.02 23.39,56.33 39.01,56.33 39.01,45.77 69.34,45.77 69.34,9.07 61.09,9.07 61.09,0.64
GND_SIGNAL on TOP (solid shape): 49.55,42.65 49.02,42.65 48.76,42.39 48.76,41.81 48.74,41.78 48.53,41.78 48.53,42.52 48.61,42.6 48.61,44.88 49.55,44.88
GND_SIGNAL on TOP (solid shape): 56.15,43.53 56.92,42.77 56.92,39.47 56.28,39.47 56.28,40.36 54.63,42.01 53.36,42.01 53.36,43.36 51.3,43.36 50.72,43.94 49.55,43.94 49.55,42.64 48.66,42.64 48.66,45.95 49.55,45.95 49.55,44.14 52.19,44.14 52.47,43.87 54,43.87 54,46.66 53.87,46.79 53.87,47.93 56.15,47.93
GND_SIGNAL on BOTTOM (solid shape): 49.55,45.69 49.55,45.31 49.68,45.18 50.57,45.18 50.57,43.28 49.68,43.28 49.55,43.15 49.55,42.9 49.3,42.64 48.92,42.64 48.79,42.77 48.79,45.69 49.04,45.95 49.3,45.95
GND_SIGNAL on INNER_LAYER2: 69.34,41.9 69.34,14.58 58.29,14.58 58.29,38.48 48.77,38.48 48.01,39.24 48.01,42.16 48.51,42.67 48.51,46.35 46.1,46.35 45.72,46.74 45.72,51.44 58.67,51.44 63.27,46.83 64.41,46.83
GND_SIGNAL on INNER_LAYER5: 69.34,46.83 69.34,14.58 58.29,14.58 58.29,38.53 48.01,38.53 48.01,42.16 48.51,42.67 48.51,46.35 46.1,46.35 45.72,46.74 45.72,51.44 58.67,51.44 63.27,46.83
VIN on TOP (solid shape): 45.36,55.93 45.36,46.66 46.07,45.95 48.15,45.95 48.15,45.06 29.56,45.06 27.71,43.2 27.71,37.18 24.99,34.47 1.8,34.47 1.8,47.34 6.93,47.34 15.9,56.31 44.98,56.31
VIN on BOTTOM (solid shape): 45.61,53.26 45.61,48.44 45.82,48.23 50.52,48.23 50.57,48.18 50.57,45.9 49.93,45.9 49.8,46.02 49.8,46.79 49.68,46.91 48.53,46.91 47.77,46.15 47.77,45.14 43.33,45.14 43.33,45.06 30.55,45.06 27.71,42.21 27.71,37.18 24.99,34.47 1.8,34.47 1.8,47.34 6.93,47.34 15.94,56.36 42.52,56.36
VIN on INNER_LAYER3, INNER_LAYER4: 0.64,33.88 0.64,47.75 9.02,47.75 9.02,56.36 48.13,56.36 48.13,45.06 28.98,45.06 27.71,43.79 27.71,37.18 24.4,33.88
VIN on INNER_LAYER5: 0.64,33.88 0.64,47.75 9.02,47.75 9.02,56.36 45.34,56.36 45.34,48.26 45.74,47.86 45.74,45.97 48.13,45.97 48.13,45.06 28.98,45.06 27.71,43.79 27.71,37.18 24.4,33.88
VO on TOP (solid shape): outline of 93 points within 1.8,1.32 57.42,25.83
VO on BOTTOM (solid shape): outline of 91 points within 1.8,1.32 57.42,25.83
VO on INNER_LAYER3: 16.66,3.65 16.66,7.46 0.64,7.46 0.64,25.45 4.39,25.45 5.46,24.38 23.95,24.38 25.8,22.53 33.86,22.53 34.16,22.23 34.16,20.95 35.26,19.86 54.12,19.86 54.12,15.16 50.82,11.86 50.82,3.65
VO on INNER_LAYER4: 15.82,0.64 15.78,0.67 15.75,0.64 8.89,0.64 8.89,7.56 7.56,8.89 0.64,8.89 0.64,25.83 9.42,25.83 9.42,24.56 21.1,24.56 22.58,23.09 38.88,23.09 38.88,21.39 57.42,21.39 57.42,11.1 56.28,9.96 52.34,9.96 50.82,8.43 50.82,0.64 ; 1 cut-out
N16775181 on TOP (solid shape): 47.26,41.45 47.65,41.07 47.65,38.79 48.49,37.94 57,37.94 57.42,37.52 57.42,27.36 39.01,27.36 39.01,35.99 40.79,37.77 41.3,37.77 45.61,42.09 47.26,42.09

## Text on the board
Ref Des/Assembly Bottom: ASSEMBLY BOTTOM
Ref Des/Silkscreen Bottom: SILK BOTTOM
User.Comments: CR_1_2
Ref Des/Assembly Top: ASSEMBLY TOP
Ref Des/Silkscreen Top: ULTRASONIC | EXT VDRV | ENABLE | MODE4 | MODE3 | MODE2 | MODE1 | + VOUT | + VIN | -VOUT | SIC46 | 3V3 | GNDIN_S | VIN_S | 5V0 | REV3 | 12V0 | SW | PGD | GNDOUT_S | VOUT_S | AGND | SILKTOP
INNER_LAYER2: INNER_LAYER2
INNER_LAYER3: INNER_LAYER3
INNER_LAYER4: INNER_LAYER4
INNER_LAYER5: INNER_LAYER5
User.16: 20.LAYER STACKUP     4 LAYERS. SEE STACK-UP DETAIL. | 17.SOLDER MASK COLOR:LIGHT BLUE (OR CLOSEST) | 22.FIDUCIALS         ADD FIDUCIALS TO PRIMARY SIDES. | 23 MATERIAL:         LEAD-FREE PROCESS | 24 COLOR:            LIGHT BLUE (OR CLOSEST) | 25 COPPER THICKNESS: SEE STACK-UP DETAIL. | 18.FINISH            SOLDER MASK OVER BARE COPPER (SMOBC) WITH | HOT AIR SOLDER LAVELING (HASL). | 19.SILKSCREEN        WHITE NONCONDUCTIVE INK. | NO INK TO APPEAR ON EXPOSED COPPER SUCH AS PLATE THROUGH HOLE PADS AND | SURFACE MOUNT LANDS. INK ON SOLDER MASK COVERED PADS IS PERMISSIBLE. | 16.SOLDER MASK       TO BE IN ACCORDANCE WITH IPC-SM-840C CLASS T. | TYPE: LIQUID PHOTOIMAGEABLE. | BRAND: CIBA-GEIGY PROBIMER 52, 65M, ENTHONE ENPLATE DSR-3241 OR EQUIVALENT. | FINISH: MATTE FINISH PREFERRED. | COLOR: LIGHT BLUE (OR CLOSEST) | REGISTRATION: TO BE WITHIN +/-0.003 OF ITS RESPECTIVE OUTER CIRCUIT LAYERS. | SOLDER MASK ENCROACHMENT ONTO SMT LANDS IS INTENTIONAL | WHERE SUPPLIED DATA DOES NOT PROVIDE CLEARANCE FROM THE PAD. | 21.TOTAL THICKNESS   0.062". | 14.Minimum immersion gold thickness  of 2uin - 8uin over a minimum of 118uin electroless nickel. | 1. PART NUMBER       P/N 133-020-0002 | 2. SIDE SHOWN        PRIMARY / SIDE 1. | 15.When applies Gold Plating and Nickel Plating For Edge-Board Connectors and | 3. DIMENSIONS        DECIMAL INCHES. | 4. BASE MATERIAL     LEAD-FREE PROCESS | 5. Tg                MINIMUM GLASS TRANSITTION TEMPERATURE (Tg) OF 170 DEGREES CELSIUS. | 6. FLAME CLASS       UL 94V-0 & MUST MEET REQUIREMENTS OF UL 796. | 7. MOT               MANUFACTURE MUST BE UL RECOGNIZED TO PRODUCE THIS PRODUCT SUCH THAT | IT MEETS 130 DEGREES CELSIUS MAXIMUM OPERATING TEMPERATURE (MOT). | 8. MARKINGS         THE FOLLOWING MUST BE MARKED OR ETCHED ON SIDE 2 OF PCB IN AREA SHOWN: | DATE CODE. | UL RECOGNIZED VENDOR ID UL TYPE DESIGNATION AND/OR MARKINGS WHICH REPLECT | THE SPECIFIED FLAME CLASS AND MAXIMUM OPERATING TEMPERATURE RATTINGS. | 9. PCB THICKNESS     0.62 +/-10% AS MESURED OVER METAL. | 10.BOW & TWIST       SHALL BE DETERMINED BY PHYSICAL MEASUREMENT AND PERCENTAGE | CALCULATION IN ACCORDANCE WITH IPC - TM - 650. METHOD 2.4.22. | 11.PLATING           MINIMUM COPPER THICKNESS  AFTER PROCESSING INTERNAL AND EXTERNAL LAYERS | IS PROVIDED BELOW IN THE LAYER STACKUP. | HOLE PLATING = 0.001 MIN. AVERAGE / 0.0008 ABSOLUTE MIN PLATING. | HOLE DIAMETERS SPECIFIED AFTER PLATING (SEE HOLE SCHEDULE). | 12.CONDUCTORS        FINISHED CONDUCTOR WIDTH: 0.010 REDUCED NO MORE THAN 20% OF NOMINAL. | FINISHED CONDUCTOR SPACING: 0.003 MINIMUM. | 13.ANNULAR RING      0.001 MINIMUM FOR INTERNAL ANNULAR RING. | 0.002 MINIMUM FOR EXTERNAL ANNULAR RING. | Unless Otherwise Specified on the Fabrication Drawing. | Non-Soldered Areas Shall be Per IPC-2221 | For none functional short gold fingers it is ok to leave the plating trace | FAB NOTES:UNLESS OTHERWISE SPECIFIED.
User.28: L02_GND1
User.29: L03_VDD
User.32: L04_PWR2
User.33: L05_GND2
User.35: 0.008 | 0.014 | 0.007 | LAYER 1    (TOP SIDE) 2.0 OZ. | LAYER 2    INNER LAYER 2 2.0 OZ. | LAYER 3    INNER LAYER 3 2.0 OZ. | LAYER 4    INNER LAYER 4 2.0 OZ. | LAYER 5    INNER LAYER 5 2.0 OZ. | LAYER 6    (BOTTOM SIDE) 2.0 OZ. | SILKSCREEN (TOP SIDE) | SOLDERMASK (TOP SIDE) | SOLDERMASK (BOTTOM SIDE) | SILKSCREEN (BOTTOM SIDE) | .00628 +/- 10% | LAYER DETAIL | 6 LAYER
User.36: L03_VDD
User.37: L2_GND1
User.38: L3_SIG1
User.39: L4_PWR1
User.40: L5_PWR2
User.41: L6_SIG2
User.42: L7_GND2
User.45: FIGURE | SIZE | 13.0 | 40.0 | 51.0 | 156.0 | DRILL CHART: TOP to BOTTOM | ALL UNITS ARE IN MILS | TOLERANCE | +3.0/-13.0 | +3.0/-3.0 | PLATED | QTY | 467 | 29 | 4
